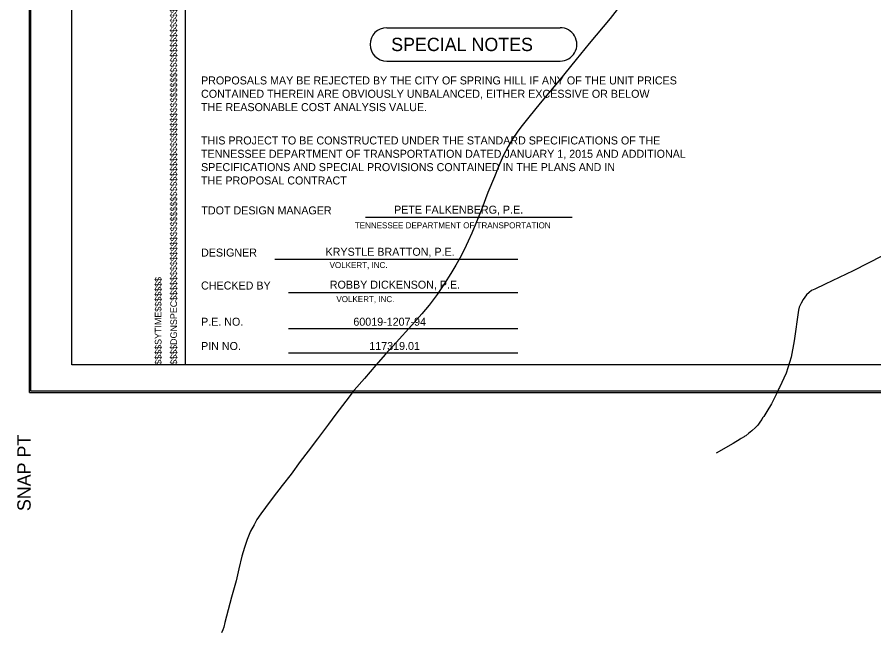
# Model space of a CAD drawing. Extents: x 1577619 to 1828281, y 483481 to 598136.
# Drawn here: x 1647095 to 1672781, y 489336 to 507802 of the extents above; entities that cross this region are included whole.
import ezdxf

# ---------------------------------------------------------------- set-up
doc = ezdxf.new("R2010")
doc.units = 0
for name, color, linetype in [('DESIGN - SHEET - Corner Text', 7, 'Continuous'), ('DESIGN - SHEET - Linework', 7, 'Continuous'), ('DESIGN - SHEET - Plot Shape', 7, 'Continuous'), ('SURVEY - CENTERLINE - Preliminary Text', 7, 'Continuous'), ('SURVEY - CONTROL with Text', 7, 'Continuous')]:
    doc.layers.add(name, color=color, linetype=linetype)

msp = doc.modelspace()

# ---------------------------------------------------------------- linework, layer by layer
at = {"layer": 'DESIGN - SHEET - Linework'}
for p, q in [((1647461, 496549), (1647461, 540205)), ((1658177, 507483), (1663377, 507483)), ((1658177, 506483), (1663377, 506483)), ((1657538, 501803), (1663738, 501803)), ((1654823, 500548), (1662110, 500548)), ((1655230, 499546), (1662110, 499546)), ((1655230, 498460), (1662110, 498460)), ((1655230, 497732), (1662110, 497732)), ((1647461, 496549), (1715541, 496549))]:
    msp.add_line(p, q, dxfattribs=at)
msp.add_lwpolyline([(1652139, 539377), (1715107, 539377), (1715107, 497377), (1652139, 497377), (1652139, 539377)], dxfattribs=at)
for centre, start, end in [((1658177, 506983), 90, 270), ((1663377, 506983), 269.7708, 90.6903)]:
    msp.add_arc(centre, 500, start, end, dxfattribs=at)
at = {"layer": 'DESIGN - SHEET - Plot Shape'}
for points in [[(1647501, 540165), (1715501, 540165), (1715501, 496589), (1647501, 496589)], [(1648737, 539377), (1715107, 539377), (1715107, 497377), (1648737, 497377)]]:
    msp.add_lwpolyline(points, close=True, dxfattribs=at)
at = {"layer": 'SURVEY - CENTERLINE - Preliminary Text'}
msp.add_lwpolyline([(1665261, 508256), (1664876, 507762), (1664247, 507012), (1663855, 506527), (1663342, 505906), (1662773, 505217), (1662434, 504800), (1662201, 504500), (1662083, 504351), (1661961, 504166), (1661816, 503925), (1661669, 503638), (1661519, 503295), (1661404, 503012), (1661208, 502539), (1661027, 502054), (1660846, 501610), (1660730, 501324), (1660619, 501081), (1660495, 500828), (1660366, 500569), (1660247, 500366), (1660100, 500111), (1659909, 499811), (1659685, 499481), (1659451, 499167), (1659224, 498899), (1658930, 498565), (1658462, 498046), (1658140, 497691), (1657850, 497361), (1657507, 496966), (1657203, 496615), (1656945, 496284), (1656650, 495894), (1656429, 495596), (1656096, 495157), (1655821, 494785), (1655584, 494471), (1655307, 494100), (1655045, 493752), (1654775, 493404), (1654545, 493101), (1654403, 492906), (1654285, 492735), (1654197, 492581), (1654091, 492386), (1653988, 492139), (1653909, 491897), (1653836, 491634), (1653740, 491254), (1653664, 490892), (1653519, 490407), (1653324, 489646), (1653288, 489510), (1653262, 489423), (1653222, 489336)], dxfattribs=at)
msp.add_lwpolyline([(1665261, 508256), (1664876, 507762), (1664247, 507012), (1663855, 506527), (1663342, 505906), (1662773, 505217), (1662434, 504800), (1662201, 504500), (1662083, 504351), (1661961, 504166), (1661816, 503925), (1661669, 503638), (1661519, 503295), (1661404, 503012), (1661208, 502539), (1661027, 502054), (1660846, 501610), (1660730, 501324), (1660619, 501081), (1660495, 500828), (1660366, 500569), (1660247, 500366), (1660100, 500111), (1659909, 499811), (1659685, 499481), (1659451, 499167), (1659224, 498899), (1658930, 498565), (1658462, 498046), (1658140, 497691), (1657850, 497361), (1657507, 496966), (1657203, 496615), (1656945, 496284), (1656650, 495894), (1656429, 495596), (1656096, 495157), (1655821, 494785), (1655584, 494471), (1655307, 494100), (1655045, 493752), (1654775, 493404), (1654545, 493101), (1654403, 492906), (1654285, 492735), (1654197, 492581), (1654091, 492386), (1653988, 492139), (1653909, 491897), (1653836, 491634), (1653740, 491254), (1653664, 490892), (1653519, 490407), (1653324, 489646), (1653288, 489510), (1653262, 489423), (1653222, 489336)], dxfattribs=at)
at = {"layer": 'SURVEY - CONTROL with Text'}
msp.add_lwpolyline([(1673042, 500647), (1672162, 500190), (1671324, 499794), (1671010, 499648), (1670915, 499599), (1670841, 499546), (1670763, 499474), (1670662, 499333), (1670601, 499225), (1670546, 499103), (1670522, 499014), (1670395, 498090), (1670300, 497604), (1670148, 497127), (1669953, 496699), (1669935, 496660), (1669880, 496543), (1669811, 496405), (1669707, 496206), (1669569, 495974), (1669479, 495829), (1669446, 495780), (1669418, 495738), (1669385, 495690), (1669359, 495654), (1669318, 495598), (1669293, 495560), (1669229, 495495), (1669120, 495394), (1669075, 495355), (1669037, 495325), (1668939, 495250), (1668916, 495233), (1668904, 495225), (1668891, 495216), (1668869, 495201), (1668807, 495161), (1668777, 495142), (1668565, 495017), (1668057, 494726)], dxfattribs=at)

# ---------------------------------------------------------------- texts
at = {"layer": 'DESIGN - SHEET - Corner Text'}
for s, height, p in [('$$$$DGNSPEC$$$$$$$$$$$$$$$$$$$$$$$$$$$$$$$$$$$$$$$$$$$$$$$$$$$$$$$$$$$$$$$$$$$$$$$$$$$$$$$$$$$$$$$$$$$$$$$$$$$$$$$$$$$$$$$$$$$', 200.004, (1651887, 497377)), ('$$$$SYTIME$$$$$$$', 200, (1651423, 497377)), ('SNAP PT  ', 400, (1647501, 492989))]:
    msp.add_text(s, height=height, rotation=90, dxfattribs=at).set_placement(p)
for s, height, p in [('SPECIAL NOTES', 400, (1658309, 506783)), ('PROPOSALS MAY BE REJECTED BY THE CITY OF SPRING HILL IF ANY OF THE UNIT PRICES', 240, (1652609, 505783)), ('CONTAINED THEREIN ARE OBVIOUSLY UNBALANCED, EITHER EXCESSIVE OR BELOW', 240, (1652609, 505383)), ('THE REASONABLE COST ANALYSIS VALUE.', 240, (1652609, 504983)), ('THIS PROJECT TO BE CONSTRUCTED UNDER THE STANDARD SPECIFICATIONS OF THE', 240, (1652609, 503983)), ('TENNESSEE DEPARTMENT OF TRANSPORTATION DATED JANUARY 1, 2015 AND ADDITIONAL', 240, (1652609, 503583)), ('SPECIFICATIONS AND SPECIAL PROVISIONS CONTAINED IN THE PLANS AND IN', 240, (1652609, 503183)), ('THE PROPOSAL CONTRACT', 240, (1652609, 502783)), ('TDOT DESIGN MANAGER', 240, (1652619, 501886)), ('PETE FALKENBERG, P.E.', 240, (1658396, 501907)), ('TENNESSEE DEPARTMENT OF TRANSPORTATION', 180, (1657219, 501468)), ('KRYSTLE BRATTON, P.E.', 240, (1656342, 500645)), ('DESIGNER', 240, (1652609, 500621)), ('VOLKERT, INC.', 180, (1656463, 500276)), ('CHECKED BY', 240, (1652609, 499633)), ('ROBBY DICKENSON, P.E.', 240, (1656470, 499658)), ('VOLKERT, INC. ', 180, (1656667, 499255)), ('P.E. NO. ', 240, (1652609, 498547)), ('60019-1207-94', 240, (1657176, 498547)), ('PIN NO. ', 240, (1652609, 497819)), ('117319.01', 240, (1657654, 497819))]:
    msp.add_text(s, height=height, dxfattribs=at).set_placement(p)

doc.saveas('drawing.dxf')
